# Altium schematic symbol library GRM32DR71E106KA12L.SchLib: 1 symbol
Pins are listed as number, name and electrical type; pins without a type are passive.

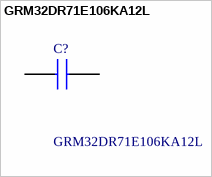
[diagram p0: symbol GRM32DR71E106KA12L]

## GRM32DR71E106KA12L
designator C?
Murata, 1210 (3225M) 10uF Multilayer Ceramic Capacitor MLCC 25V dc +/-10% , SMD GRM32DR71E106KA12L; Manufacturer_Name: Murata Electronics; Geometry.Height: 2mm
footprint GRM32DR61C106KA01L
pins: 1, 2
